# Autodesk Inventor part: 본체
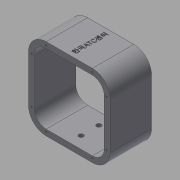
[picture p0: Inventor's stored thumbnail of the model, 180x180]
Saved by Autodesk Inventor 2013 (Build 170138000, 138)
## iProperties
Created: 2016-12
Part Number: 본체
Material: 일반
Document SubType Name: Modeling
Designer: mduedu
Density: 1 g/cm^3
Author: mduedu
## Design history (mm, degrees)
sketch "스케치1"
  geometry: L1 (-46, 42)-(-46, -36); L2 (-16, 72)-(62, 72); L3 (92, 42)-(92, -36); L4 (62, -66)-(-16, -66); A1 r 30 centre (-16, -36) between (-46, -36) and (-16, -66); A2 r 30 centre (62, 42) between (92, 42) and (62, 72); A3 r 30 centre (62, -36) between (62, -66) and (92, -36); A4 r 30 centre (-16, 42) between (-16, 72) and (-46, 42); 1 further point
  constraints: 8 end point, 8 point on circle, 8 tangent, 4 centre point, 3 equal radius, 1 horizontal, 1 perpendicular, 1 vertical
  dimensions: "d83" = 30 radius of A2; "d84" = 92 distance from line of L3 point (0, 0); "d85" = 138 distance between parallel lines of L4 L2; "d86" = 46 distance from line of L1 point (0, 0); "d87" = 72 distance from line of point (0, 0) L2
extrude "돌출1" new body sketch "스케치1" stored distance "d3" = 70; taper "d4" = 0 deg
feature "쉘1" dims "d5" = 10
sketch "스케치10"
  geometry: L1 (78, 70)-(0, 70) reference; L2 (-30, 70)-(-30, 0) reference; 4 further points
  constraints: 1 coincident, 1 horizontal alignment, 1 midpoint, 1 vertical alignment, 1 other
  dimensions: "d88" = 35 distance of point (39, 35) point (39, 70) (derived); "d89" = 69 distance from line of point (39, 35) L2 (derived)
feature "엠보싱1" sketch "스케치10" dims "d61" = 0.5, "d62" = 0, "d83" = 30, "d84" = 92, "d85" = 138, "d86" = 46, "d87" = 72
sketch "스케치11"
  geometry: L1 (-36, -36)-(-36, 42) reference; L2 (-16, 62)-(62, 62) reference; L3 (82, 42)-(82, -36) reference; L4 (62, -56)-(-16, -56) reference; L5 (-16, -66)-(62, -66) reference; L6 (92, -36)-(92, 42) reference; L7 (62, 72)-(-16, 72) reference; L8 (-46, 42)-(-46, -36) reference; L9 (-16, 66)-(62, 66); L10 (86, 42)-(86, -36); L11 (62, -60)-(-16, -60); L12 (-40, -36)-(-40, 42); A1 r 20 centre (-16, -36) between (-36, -36) and (-16, -56) reference; A2 r 20 centre (-16, 42) between (-16, 62) and (-36, 42) reference; A3 r 20 centre (62, 42) between (82, 42) and (62, 62) reference; A4 r 20 centre (62, -36) between (62, -56) and (82, -36) reference; A5 r 30 centre (-16, -36) between (-46, -36) and (-16, -66) reference; A6 r 30 centre (62, -36) between (62, -66) and (92, -36) reference; A7 r 30 centre (62, 42) between (92, 42) and (62, 72) reference; A8 r 30 centre (-16, 42) between (-16, 72) and (-46, 42) reference; A9 r 24 centre (62, 42) between (86, 42) and (62, 66); A10 r 24 centre (62, -36) between (62, -60) and (86, -36); A11 r 24 centre (-16, -36) between (-40, -36) and (-16, -60); A12 r 24 centre (-16, 42) between (-16, 66) and (-40, 42); 8 further points
  constraints: 8 coincident, 8 end point, 8 point on circle, 4 centre point, 7 other
  dimensions: "d90" = 6 distance between parallel lines of L9 L7
hole "구멍3" sketch "스케치11" at (-16, 66), (-40, 42), (-40, -36), (-16, -60), (62, -60), (86, -36), (86, 42), (62, 66) diameter "d63" = 3.242; stored, may be unused: countersink angle "d67" = 90 deg, drill point angle "d69" = 120 deg; dims "d64" = 8.6, "d65" = 4, "d66" = 2, "d68" = 10.6
sketch "스케치12"
  geometry: L1 (16, -56)-(-62, -56) reference; L2 (-82, -36)-(-82, 42) reference; L3 (-62, 62)-(16, 62) reference; L4 (36, 42)-(36, -36) reference; L5 (46, -36)-(46, 42) reference; L6 (16, 72)-(-62, 72) reference; L7 (-92, 42)-(-92, -36) reference; L8 (-62, -66)-(16, -66) reference; L9 (-62, 66)-(16, 66); L10 (40, 42)-(40, -36); L11 (16, -60)-(-62, -60); L12 (-86, -36)-(-86, 42); A1 r 20 centre (16, -36) between (16, -56) and (36, -36) reference; A2 r 20 centre (-62, -36) between (-82, -36) and (-62, -56) reference; A3 r 20 centre (-62, 42) between (-62, 62) and (-82, 42) reference; A4 r 20 centre (16, 42) between (36, 42) and (16, 62) reference; A5 r 30 centre (16, -36) between (16, -66) and (46, -36) reference; A6 r 30 centre (16, 42) between (46, 42) and (16, 72) reference; A7 r 30 centre (-62, 42) between (-62, 72) and (-92, 42) reference; A8 r 30 centre (-62, -36) between (-92, -36) and (-62, -66) reference; A9 r 24 centre (16, 42) between (40, 42) and (16, 66); A10 r 24 centre (16, -36) between (16, -60) and (40, -36); A11 r 24 centre (-62, -36) between (-86, -36) and (-62, -60); A12 r 24 centre (-62, 42) between (-62, 66) and (-86, 42); 8 further points
  constraints: 8 coincident, 8 end point, 8 point on circle, 4 centre point, 7 other
  dimensions: "d91" = 6 distance between parallel lines of L9 L6
hole "구멍5" sketch "스케치12" at (-62, 66), (-86, 42), (-86, -36), (-62, -60), (16, -60), (40, -36), (40, 42), (16, 66) diameter "d70" = 3.242; stored, may be unused: countersink angle "d74" = 90 deg, drill point angle "d76" = 120 deg; dims "d71" = 8.6, "d72" = 4, "d73" = 2, "d75" = 10.6
sketch "스케치15"
  geometry: L1 (135.6, -35)-(-57.6, -35) reference; L2 (78, 0)-(0, 0) reference; L3 (0, -70)-(78, -70) reference; L4 (39, 0)-(39, -70); C1 r 4 at (39, -20); C2 r 4 at (39, -50); 1 further point
  constraints: 2 centre point, 2 end point, 2 midpoint, 1 point on line, 1 symmetric about line, 1 other
  dimensions: "d92" = 8 diameter of C1; "d93" = 15 distance from line of C1.centre L1
extrude "돌출6" cut sketch "스케치15" stored distance "d94" = 10; taper "d95" = 0 deg
node "솔리드1"
node "투영된 루프3"
node "투영된 루프4"
